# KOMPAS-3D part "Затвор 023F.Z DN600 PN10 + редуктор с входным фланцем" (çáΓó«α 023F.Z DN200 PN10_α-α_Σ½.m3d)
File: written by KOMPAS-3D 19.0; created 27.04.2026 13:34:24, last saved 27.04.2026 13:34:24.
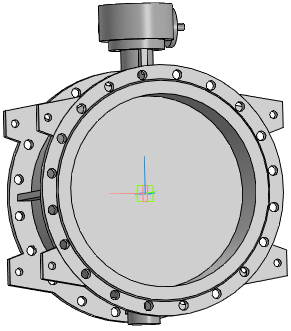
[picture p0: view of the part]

Document properties: Полное имя файла: ..\..\Затвор 023F.Z DN200-DN1600_редуктор с входным фланцем\Затвор 023F.Z DN600 PN10 + редуктор с входным фланцем.a3d

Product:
- Part/product: Затвор 023F.Z DN600 PN10 + редуктор с входным фланцем
    Масса: 386.006

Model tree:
1. Операция без истории:1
